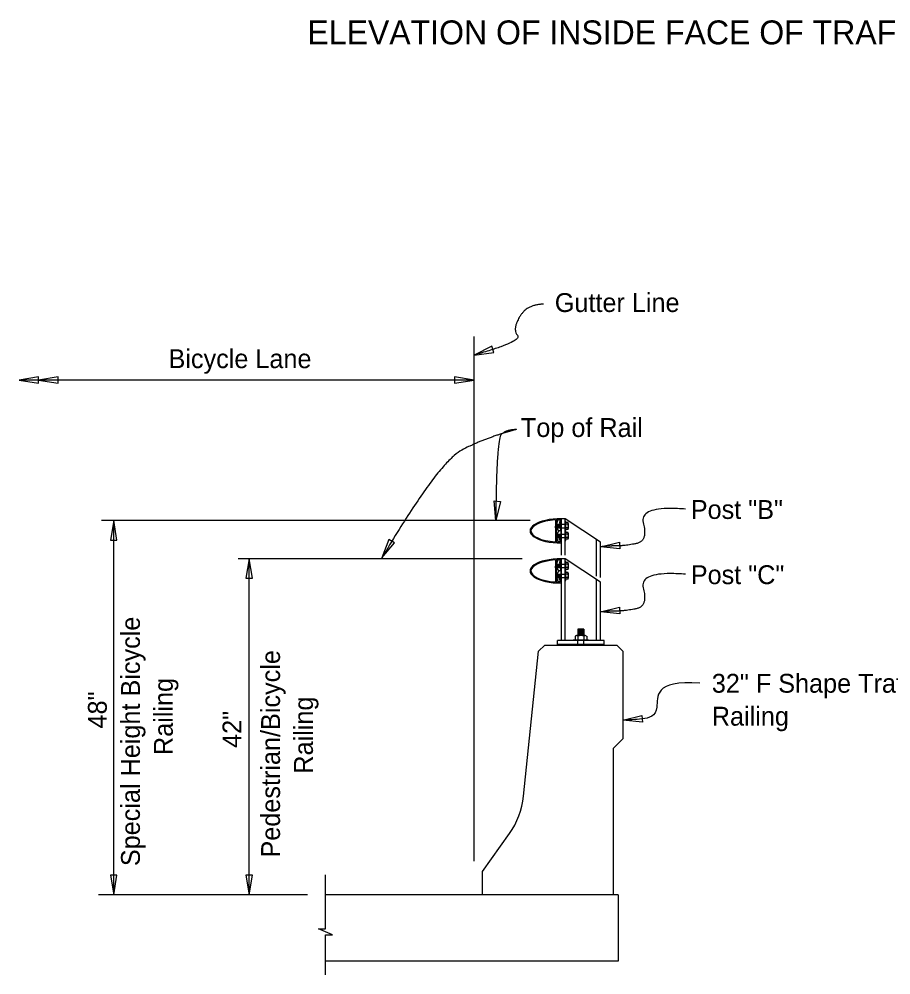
# Model space of a CAD drawing. Extents: x 120680.2 to 120752.3, y 120667.6 to 120707.3.
# Drawn here: x 120686.53 to 120695.85, y 120684.08 to 120694.3 of the extents above; entities that cross this region are included whole.
import ezdxf

# ---------------------------------------------------------------- set-up
doc = ezdxf.new("R2010")
doc.units = 0
for name, color, linetype in [('Dimension', 7, 'Continuous'), ('ParapetConc', 7, 'Continuous'), ('PedRail', 7, 'Continuous'), ('TextStructures', 7, 'Continuous')]:
    doc.layers.add(name, color=color, linetype=linetype)

# ---------------------------------------------------------------- blocks, each defined once
blk = doc.blocks.new('Terminator-DblArrow')
at = {"layer": 'Dimension'}
for points in [[(-0.00651, 0), (-0.01302, 0.0011), (-0.01302, -0.0011)], [(0, 0), (-0.00651, 0.0011), (-0.00651, -0.0011)]]:
    blk.add_lwpolyline(points, close=True, dxfattribs=at)

msp = doc.modelspace()

# ---------------------------------------------------------------- linework, layer by layer
at = {"layer": 'Dimension'}
for p, q in [((120691.391, 120685.298), (120691.391, 120690.904)), ((120691.391, 120690.44), (120686.526, 120690.44)), ((120691.992, 120688.937), (120687.407, 120688.937)), ((120687.538, 120684.937), (120687.538, 120688.937)), ((120691.906, 120688.53), (120688.868, 120688.53)), ((120688.988, 120684.937), (120688.988, 120688.53)), ((120689.611, 120684.937), (120687.375, 120684.937))]:
    msp.add_line(p, q, dxfattribs=at)
for points in [[(120691.391, 120690.707), (120691.601, 120690.734), (120691.58, 120690.802)], [(120691.391, 120690.44), (120691.183, 120690.475), (120691.183, 120690.405)], [(120691.622, 120688.937), (120691.605, 120689.148), (120691.675, 120689.142)], [(120687.538, 120688.937), (120687.503, 120688.729), (120687.573, 120688.729)], [(120690.405, 120688.538), (120690.541, 120688.7), (120690.48, 120688.735)], [(120692.741, 120688.656), (120692.947, 120688.706), (120692.951, 120688.636)], [(120688.988, 120688.53), (120688.952, 120688.321), (120689.023, 120688.321)], [(120692.741, 120687.96), (120692.947, 120688.01), (120692.951, 120687.939)], [(120692.981, 120686.802), (120693.186, 120686.852), (120693.191, 120686.781)], [(120687.538, 120684.937), (120687.573, 120685.146), (120687.503, 120685.146)], [(120688.988, 120684.937), (120689.023, 120685.146), (120688.952, 120685.146)]]:
    msp.add_lwpolyline(points, close=True, dxfattribs=at)
msp.add_lwpolyline([(120689.801, 120684.081), (120689.801, 120684.508), (120689.878, 120684.508), (120689.728, 120684.574), (120689.801, 120684.574), (120689.801, 120685.15)], dxfattribs=at)
for points, degree in [([(120692.135, 120691.25), (120691.958, 120691.25), (120691.799, 120690.983), (120691.911, 120690.852), (120691.391, 120690.707)], 2), ([(120691.846, 120689.91), (120691.52, 120689.827), (120691.009, 120689.561), (120690.405, 120688.538)], 2), ([(120691.846, 120689.91), (120691.725, 120689.908), (120691.631, 120689.8), (120691.622, 120688.937)], 2), ([(120693.65, 120689.06), (120693.15, 120689.1), (120693.25, 120688.718), (120693.008, 120688.667), (120692.822, 120688.666), (120692.741, 120688.656)], 2), ([(120693.65, 120688.364), (120693.15, 120688.403), (120693.25, 120688.021), (120693.008, 120687.971), (120692.822, 120687.969), (120692.741, 120687.96)], 2), ([(120693.806, 120687.199), (120693.306, 120687.238), (120693.406, 120686.856), (120693.191, 120686.811), (120693.039, 120686.806), (120692.981, 120686.802)], 3)]:
    msp.add_open_spline(points, degree=degree, dxfattribs=at)
at = {"layer": 'ParapetConc'}
for p, q in [((120691.92, 120685.991), (120692.079, 120687.542)), ((120692.079, 120687.542), (120692.148, 120687.604)), ((120692.079, 120687.542), (120692.148, 120687.604)), ((120692.148, 120687.604), (120692.918, 120687.604)), ((120692.148, 120687.604), (120692.283, 120687.604)), ((120692.918, 120687.604), (120692.981, 120687.542)), ((120692.981, 120687.542), (120692.981, 120686.604)), ((120692.981, 120686.604), (120692.877, 120686.5)), ((120692.877, 120686.5), (120692.877, 120684.937)), ((120691.481, 120684.937), (120689.801, 120684.937)), ((120692.877, 120684.937), (120691.481, 120684.937)), ((120692.933, 120684.937), (120692.877, 120684.937)), ((120692.933, 120684.937), (120692.933, 120684.229)), ((120692.933, 120684.229), (120689.801, 120684.229))]:
    msp.add_line(p, q, dxfattribs=at)
msp.add_lwpolyline([(120691.481, 120684.937), (120691.481, 120685.187), (120691.769, 120685.591)], dxfattribs=at)
msp.add_arc((120691.091, 120686.075), 0.833, 324.4565, 354.1603, dxfattribs=at)
at = {"layer": 'PedRail'}
for p, q in [((120692.322, 120688.91), (120692.322, 120688.957)), ((120692.325, 120688.566), (120692.325, 120688.957)), ((120692.366, 120688.566), (120692.366, 120688.957)), ((120692.262, 120688.858), (120692.262, 120688.879)), ((120692.263, 120688.94), (120692.263, 120688.713)), ((120692.27, 120688.945), (120692.27, 120688.709)), ((120692.272, 120688.898), (120692.289, 120688.944)), ((120692.272, 120688.861), (120692.272, 120688.898)), ((120692.272, 120688.898), (120692.325, 120688.898)), ((120692.299, 120688.827), (120692.272, 120688.861)), ((120692.272, 120688.861), (120692.325, 120688.861)), ((120692.278, 120688.892), (120692.278, 120688.867)), ((120692.283, 120688.898), (120692.283, 120688.861)), ((120692.288, 120688.892), (120692.288, 120688.867)), ((120692.31, 120688.944), (120692.289, 120688.944)), ((120692.294, 120688.898), (120692.294, 120688.861)), ((120692.299, 120688.892), (120692.299, 120688.867)), ((120692.304, 120688.898), (120692.304, 120688.861)), ((120692.31, 120688.924), (120692.305, 120688.924)), ((120692.305, 120688.924), (120692.305, 120688.908)), ((120692.305, 120688.908), (120692.318, 120688.908)), ((120692.307, 120688.921), (120692.307, 120688.91)), ((120692.307, 120688.921), (120692.312, 120688.921)), ((120692.307, 120688.91), (120692.322, 120688.91)), ((120692.31, 120688.944), (120692.31, 120688.924)), ((120692.31, 120688.892), (120692.31, 120688.867)), ((120692.312, 120688.921), (120692.312, 120688.947)), ((120692.315, 120688.898), (120692.315, 120688.861)), ((120692.318, 120688.843), (120692.318, 120688.908)), ((120692.32, 120688.892), (120692.32, 120688.867)), ((120692.325, 120688.898), (120692.366, 120688.898)), ((120692.325, 120688.861), (120692.366, 120688.861)), ((120692.371, 120688.928), (120692.367, 120688.928)), ((120692.367, 120688.83), (120692.367, 120688.928)), ((120692.367, 120688.864), (120692.367, 120688.864)), ((120692.371, 120688.83), (120692.371, 120688.928)), ((120692.396, 120688.916), (120692.371, 120688.916)), ((120692.396, 120688.898), (120692.371, 120688.898)), ((120692.396, 120688.861), (120692.371, 120688.861)), ((120692.399, 120688.883), (120692.399, 120688.907)), ((120692.399, 120688.852), (120692.399, 120688.883)), ((120692.262, 120688.796), (120692.262, 120688.775)), ((120692.299, 120688.827), (120692.272, 120688.793)), ((120692.272, 120688.793), (120692.272, 120688.756)), ((120692.272, 120688.793), (120692.325, 120688.793)), ((120692.272, 120688.756), (120692.289, 120688.709)), ((120692.272, 120688.756), (120692.325, 120688.756)), ((120692.278, 120688.787), (120692.278, 120688.762)), ((120692.283, 120688.793), (120692.283, 120688.756)), ((120692.288, 120688.787), (120692.288, 120688.762)), ((120692.294, 120688.793), (120692.294, 120688.756)), ((120692.32, 120688.827), (120692.299, 120688.827)), ((120692.32, 120688.827), (120692.299, 120688.827)), ((120692.299, 120688.787), (120692.299, 120688.762)), ((120692.304, 120688.793), (120692.304, 120688.756)), ((120692.305, 120688.73), (120692.305, 120688.746)), ((120692.305, 120688.746), (120692.318, 120688.746)), ((120692.31, 120688.787), (120692.31, 120688.762)), ((120692.315, 120688.793), (120692.315, 120688.756)), ((120692.32, 120688.843), (120692.318, 120688.843)), ((120692.32, 120688.811), (120692.318, 120688.811)), ((120692.318, 120688.811), (120692.318, 120688.793)), ((120692.318, 120688.793), (120692.318, 120688.756)), ((120692.318, 120688.756), (120692.318, 120688.746)), ((120692.32, 120688.827), (120692.32, 120688.843)), ((120692.32, 120688.827), (120692.32, 120688.811)), ((120692.32, 120688.787), (120692.32, 120688.762)), ((120692.325, 120688.793), (120692.366, 120688.793)), ((120692.325, 120688.756), (120692.366, 120688.756)), ((120692.367, 120688.83), (120692.371, 120688.83)), ((120692.371, 120688.824), (120692.367, 120688.824)), ((120692.367, 120688.725), (120692.367, 120688.824)), ((120692.367, 120688.759), (120692.367, 120688.759)), ((120692.396, 120688.843), (120692.371, 120688.843)), ((120692.371, 120688.725), (120692.371, 120688.824)), ((120692.396, 120688.811), (120692.371, 120688.811)), ((120692.396, 120688.793), (120692.371, 120688.793)), ((120692.396, 120688.756), (120692.371, 120688.756)), ((120692.399, 120688.778), (120692.399, 120688.802)), ((120692.399, 120688.747), (120692.399, 120688.778)), ((120692.31, 120688.709), (120692.289, 120688.709)), ((120692.31, 120688.73), (120692.305, 120688.73)), ((120692.307, 120688.733), (120692.307, 120688.743)), ((120692.307, 120688.743), (120692.322, 120688.743)), ((120692.307, 120688.733), (120692.312, 120688.733)), ((120692.31, 120688.709), (120692.31, 120688.73)), ((120692.312, 120688.733), (120692.312, 120688.707)), ((120692.322, 120688.743), (120692.322, 120688.697)), ((120692.367, 120688.725), (120692.371, 120688.725)), ((120692.396, 120688.738), (120692.371, 120688.738)), ((120692.7, 120688.343), (120692.7, 120688.735)), ((120692.741, 120688.33), (120692.741, 120688.707)), ((120692.262, 120688.431), (120692.262, 120688.451)), ((120692.263, 120688.513), (120692.263, 120688.286)), ((120692.27, 120688.518), (120692.27, 120688.281)), ((120692.272, 120688.47), (120692.289, 120688.517)), ((120692.272, 120688.434), (120692.272, 120688.47)), ((120692.272, 120688.47), (120692.325, 120688.47)), ((120692.278, 120688.465), (120692.278, 120688.439)), ((120692.283, 120688.47), (120692.283, 120688.434)), ((120692.288, 120688.465), (120692.288, 120688.439)), ((120692.31, 120688.517), (120692.289, 120688.517)), ((120692.294, 120688.47), (120692.294, 120688.434)), ((120692.299, 120688.465), (120692.299, 120688.439)), ((120692.304, 120688.47), (120692.304, 120688.434)), ((120692.31, 120688.496), (120692.305, 120688.496)), ((120692.305, 120688.496), (120692.305, 120688.481)), ((120692.305, 120688.481), (120692.318, 120688.481)), ((120692.307, 120688.493), (120692.307, 120688.483)), ((120692.307, 120688.493), (120692.312, 120688.493)), ((120692.307, 120688.483), (120692.322, 120688.483)), ((120692.31, 120688.517), (120692.31, 120688.496)), ((120692.31, 120688.465), (120692.31, 120688.439)), ((120692.312, 120688.493), (120692.312, 120688.519)), ((120692.315, 120688.47), (120692.315, 120688.434)), ((120692.318, 120688.415), (120692.318, 120688.481)), ((120692.32, 120688.465), (120692.32, 120688.439)), ((120692.322, 120688.483), (120692.322, 120688.53)), ((120692.325, 120687.655), (120692.325, 120688.53)), ((120692.325, 120688.47), (120692.366, 120688.47)), ((120692.366, 120687.655), (120692.366, 120688.53)), ((120692.371, 120688.501), (120692.367, 120688.501)), ((120692.367, 120688.403), (120692.367, 120688.501)), ((120692.371, 120688.403), (120692.371, 120688.501)), ((120692.396, 120688.488), (120692.371, 120688.488)), ((120692.396, 120688.47), (120692.371, 120688.47)), ((120692.399, 120688.455), (120692.399, 120688.479)), ((120692.399, 120688.425), (120692.399, 120688.455)), ((120692.262, 120688.368), (120692.262, 120688.347)), ((120692.299, 120688.4), (120692.272, 120688.434)), ((120692.272, 120688.434), (120692.325, 120688.434)), ((120692.299, 120688.399), (120692.272, 120688.365)), ((120692.272, 120688.365), (120692.272, 120688.329)), ((120692.272, 120688.365), (120692.325, 120688.365)), ((120692.278, 120688.36), (120692.278, 120688.334)), ((120692.283, 120688.365), (120692.283, 120688.329)), ((120692.288, 120688.36), (120692.288, 120688.334)), ((120692.294, 120688.365), (120692.294, 120688.329)), ((120692.32, 120688.4), (120692.299, 120688.4)), ((120692.32, 120688.399), (120692.299, 120688.399)), ((120692.299, 120688.36), (120692.299, 120688.334)), ((120692.304, 120688.365), (120692.304, 120688.329)), ((120692.31, 120688.36), (120692.31, 120688.334)), ((120692.315, 120688.365), (120692.315, 120688.329)), ((120692.32, 120688.415), (120692.318, 120688.415)), ((120692.32, 120688.383), (120692.318, 120688.383)), ((120692.318, 120688.383), (120692.318, 120688.365)), ((120692.318, 120688.365), (120692.318, 120688.329)), ((120692.32, 120688.4), (120692.32, 120688.415)), ((120692.32, 120688.399), (120692.32, 120688.383)), ((120692.32, 120688.36), (120692.32, 120688.334)), ((120692.325, 120688.434), (120692.366, 120688.434)), ((120692.325, 120688.365), (120692.366, 120688.365)), ((120692.367, 120688.437), (120692.367, 120688.437)), ((120692.367, 120688.403), (120692.371, 120688.403)), ((120692.371, 120688.396), (120692.367, 120688.396)), ((120692.367, 120688.298), (120692.367, 120688.396)), ((120692.396, 120688.434), (120692.371, 120688.434)), ((120692.396, 120688.415), (120692.371, 120688.415)), ((120692.371, 120688.298), (120692.371, 120688.396)), ((120692.396, 120688.383), (120692.371, 120688.383)), ((120692.396, 120688.365), (120692.371, 120688.365)), ((120692.399, 120688.35), (120692.399, 120688.374)), ((120692.399, 120688.32), (120692.399, 120688.35)), ((120692.272, 120688.329), (120692.289, 120688.282)), ((120692.272, 120688.329), (120692.325, 120688.329)), ((120692.31, 120688.282), (120692.289, 120688.282)), ((120692.305, 120688.303), (120692.305, 120688.318)), ((120692.305, 120688.318), (120692.318, 120688.318)), ((120692.31, 120688.303), (120692.305, 120688.303)), ((120692.307, 120688.306), (120692.307, 120688.316)), ((120692.307, 120688.316), (120692.322, 120688.316)), ((120692.307, 120688.306), (120692.312, 120688.306)), ((120692.31, 120688.282), (120692.31, 120688.303)), ((120692.312, 120688.306), (120692.312, 120688.28)), ((120692.318, 120688.329), (120692.318, 120688.318)), ((120692.322, 120688.316), (120692.322, 120688.269)), ((120692.325, 120688.329), (120692.366, 120688.329)), ((120692.367, 120688.332), (120692.367, 120688.332)), ((120692.367, 120688.298), (120692.371, 120688.298)), ((120692.396, 120688.329), (120692.371, 120688.329)), ((120692.396, 120688.311), (120692.371, 120688.311)), ((120692.7, 120687.655), (120692.7, 120688.307)), ((120692.741, 120687.655), (120692.741, 120688.28)), ((120692.565, 120687.778), (120692.501, 120687.778)), ((120692.501, 120687.778), (120692.501, 120687.708)), ((120692.565, 120687.761), (120692.501, 120687.761)), ((120692.565, 120687.745), (120692.501, 120687.745)), ((120692.565, 120687.728), (120692.501, 120687.728)), ((120692.558, 120687.77), (120692.508, 120687.77)), ((120692.558, 120687.753), (120692.508, 120687.753)), ((120692.558, 120687.736), (120692.508, 120687.736)), ((120692.565, 120687.778), (120692.565, 120687.708)), ((120692.783, 120687.655), (120692.283, 120687.655)), ((120692.283, 120687.613), (120692.283, 120687.655)), ((120692.616, 120687.66), (120692.45, 120687.66)), ((120692.45, 120687.66), (120692.45, 120687.655)), ((120692.616, 120687.655), (120692.45, 120687.655)), ((120692.471, 120687.703), (120692.471, 120687.66)), ((120692.528, 120687.708), (120692.487, 120687.708)), ((120692.565, 120687.711), (120692.501, 120687.711)), ((120692.502, 120687.703), (120692.502, 120687.66)), ((120692.502, 120687.613), (120692.502, 120687.655)), ((120692.558, 120687.72), (120692.508, 120687.72)), ((120692.579, 120687.708), (120692.528, 120687.708)), ((120692.558, 120687.655), (120692.558, 120687.655)), ((120692.564, 120687.703), (120692.564, 120687.66)), ((120692.564, 120687.613), (120692.564, 120687.655)), ((120692.595, 120687.703), (120692.595, 120687.66)), ((120692.616, 120687.655), (120692.616, 120687.66)), ((120692.783, 120687.613), (120692.783, 120687.655)), ((120692.783, 120687.613), (120692.283, 120687.613)), ((120692.783, 120687.612), (120692.283, 120687.612)), ((120692.783, 120687.611), (120692.283, 120687.611)), ((120692.783, 120687.61), (120692.283, 120687.61)), ((120692.783, 120687.609), (120692.283, 120687.609)), ((120692.783, 120687.608), (120692.283, 120687.608)), ((120692.783, 120687.607), (120692.283, 120687.607)), ((120692.783, 120687.606), (120692.283, 120687.606)), ((120692.783, 120687.605), (120692.283, 120687.605)), ((120692.783, 120687.604), (120692.283, 120687.604)), ((120692.558, 120687.605), (120692.508, 120687.605))]:
    msp.add_line(p, q, dxfattribs=at)
for points in [[(120692.741, 120688.707), (120692.366, 120688.957), (120692.366, 120688.957), (120692.325, 120688.957)], [(120692.741, 120688.28), (120692.366, 120688.53), (120692.366, 120688.53), (120692.325, 120688.53)]]:
    msp.add_lwpolyline(points, dxfattribs=at)
for centre, radius, start, end in [((120692.384, 120688.907), 0.0147, 321.7646, 38.235), ((120692.345, 120688.879), 0.0543, 340.3688, 19.6312), ((120692.384, 120688.852), 0.0147, 321.7645, 38.2365), ((120692.384, 120688.802), 0.0147, 321.7646, 38.235), ((120692.345, 120688.774), 0.0543, 340.3688, 19.6312), ((120692.384, 120688.747), 0.0147, 321.7645, 38.2365), ((120692.384, 120688.479), 0.0147, 321.7646, 38.235), ((120692.345, 120688.452), 0.0543, 340.3688, 19.6312), ((120692.384, 120688.425), 0.0147, 321.7645, 38.2365), ((120692.384, 120688.374), 0.0147, 321.7646, 38.235), ((120692.345, 120688.347), 0.0543, 340.3688, 19.6312), ((120692.384, 120688.32), 0.0147, 321.7645, 38.2365), ((120692.486, 120687.683), 0.0249, 51.7646, 128.235), ((120692.533, 120687.616), 0.092, 70.3688, 109.6312), ((120692.579, 120687.683), 0.0249, 51.7645, 128.2365)]:
    msp.add_arc(centre, radius, start, end, dxfattribs=at)
for centre, major_axis, ratio, start_param, end_param in [((120692.322, 120688.827), (0.333, 0), 0.390781, 1.570796, 4.712389), ((120692.322, 120688.827), (0.323, 0), 0.37113, 1.77211, 4.511099), ((120692.258, 120688.94), (0.00469, 0), 0.822222, 0, 1.570796), ((120692.322, 120688.827), (0.323, 0), 0.37113, 1.60306, 1.732793), ((120692.258, 120688.713), (0.00469, 0), 0.822222, 4.712389, 6.283185), ((120692.322, 120688.827), (0.323, 0), 0.37113, 4.550392, 4.680125), ((120692.322, 120688.399), (0.333, 0), 0.390781, 1.570796, 4.712389), ((120692.322, 120688.399), (0.323, 0), 0.37113, 1.77211, 4.511099), ((120692.258, 120688.513), (0.00469, 0), 0.822222, 0, 1.570796), ((120692.322, 120688.399), (0.323, 0), 0.37113, 1.60306, 1.732793), ((120692.258, 120688.286), (0.00469, 0), 0.822222, 4.712389, 6.283185), ((120692.322, 120688.399), (0.323, 0), 0.37113, 4.550392, 4.680125)]:
    msp.add_ellipse(centre, major_axis=major_axis, ratio=ratio, start_param=start_param, end_param=end_param, dxfattribs=at)

# ---------------------------------------------------------------- block references
at = {"layer": 'TextStructures', "xscale": 31.993740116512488, "yscale": 31.909096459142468, "rotation": -180}
msp.add_blockref('Terminator-DblArrow', (120686.526, 120690.44), dxfattribs=at)

# ---------------------------------------------------------------- texts
at = {"layer": 'Dimension'}
for s, p in [('32" F Shape Traffic', (120693.933, 120687.097)), ('Railing ', (120693.933, 120686.745))]:
    msp.add_text(s, height=0.2016, dxfattribs=at).set_placement(p)
at = {"layer": 'TextStructures'}
for s, height, p in [('ELEVATION OF INSIDE FACE OF TRAFFIC RAILING WITH PEDESTRIAN/BICYCLE BULLET RAILING', 0.256, (120689.609, 120694.028)), ('Gutter Line', 0.2016, (120692.254, 120691.167)), ('Bicycle Lane', 0.2016, (120688.124, 120690.567)), ('Top of Rail', 0.2016, (120691.892, 120689.831)), ('Post "B"', 0.2016, (120693.708, 120688.955)), ('Post "C"', 0.2016, (120693.708, 120688.258))]:
    msp.add_text(s, height=height, dxfattribs=at).set_placement(p)
for s, p in [('Special Height Bicycle', (120687.818, 120685.243)), ('Pedestrian/Bicycle', (120689.316, 120685.335)), ('Railing', (120688.17, 120686.431)), ('48"', (120687.464, 120686.715)), ('Railing', (120689.668, 120686.232)), ('42"', (120688.903, 120686.507))]:
    msp.add_text(s, height=0.2016, rotation=90, dxfattribs=at).set_placement(p)

doc.saveas('drawing.dxf')
